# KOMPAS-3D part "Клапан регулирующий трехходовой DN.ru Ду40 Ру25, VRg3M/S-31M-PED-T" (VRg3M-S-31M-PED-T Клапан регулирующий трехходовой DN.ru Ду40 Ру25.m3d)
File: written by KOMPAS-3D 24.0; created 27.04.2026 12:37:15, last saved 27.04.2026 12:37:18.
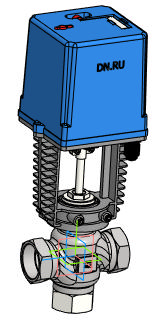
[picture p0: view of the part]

Document properties: Автор: DN.RU; Полное имя файла: D:\PROJECT CAD\DN.RU\198(ACTUALE). VRg3M-S-31M-PED-T Клапан регулирующий трехходовой DN.ru\Исходники\DN40\VRg3M-S-31M-PED-T Клапан регулирующий трехходовой DN.ru Ду40 Ру25.m3d

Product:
- Body: Твердое тело1  | qty 1
    Масса: 20.912405
- Part/product: Клапан регулирующий трехходовой DN.ru Ду40 Ру25  | designation VRg3M/S-31M-PED-T
    Масса: 4.1
    Раздел спецификации: Прочие изделия
    Комментарий: D230-11267
    Примечание: D230-11267
    additional columns: Типовые

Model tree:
1. Твердое тело1  (labels: Твердое тело1)

Expressions: VRg3M/S-31M-PED-T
